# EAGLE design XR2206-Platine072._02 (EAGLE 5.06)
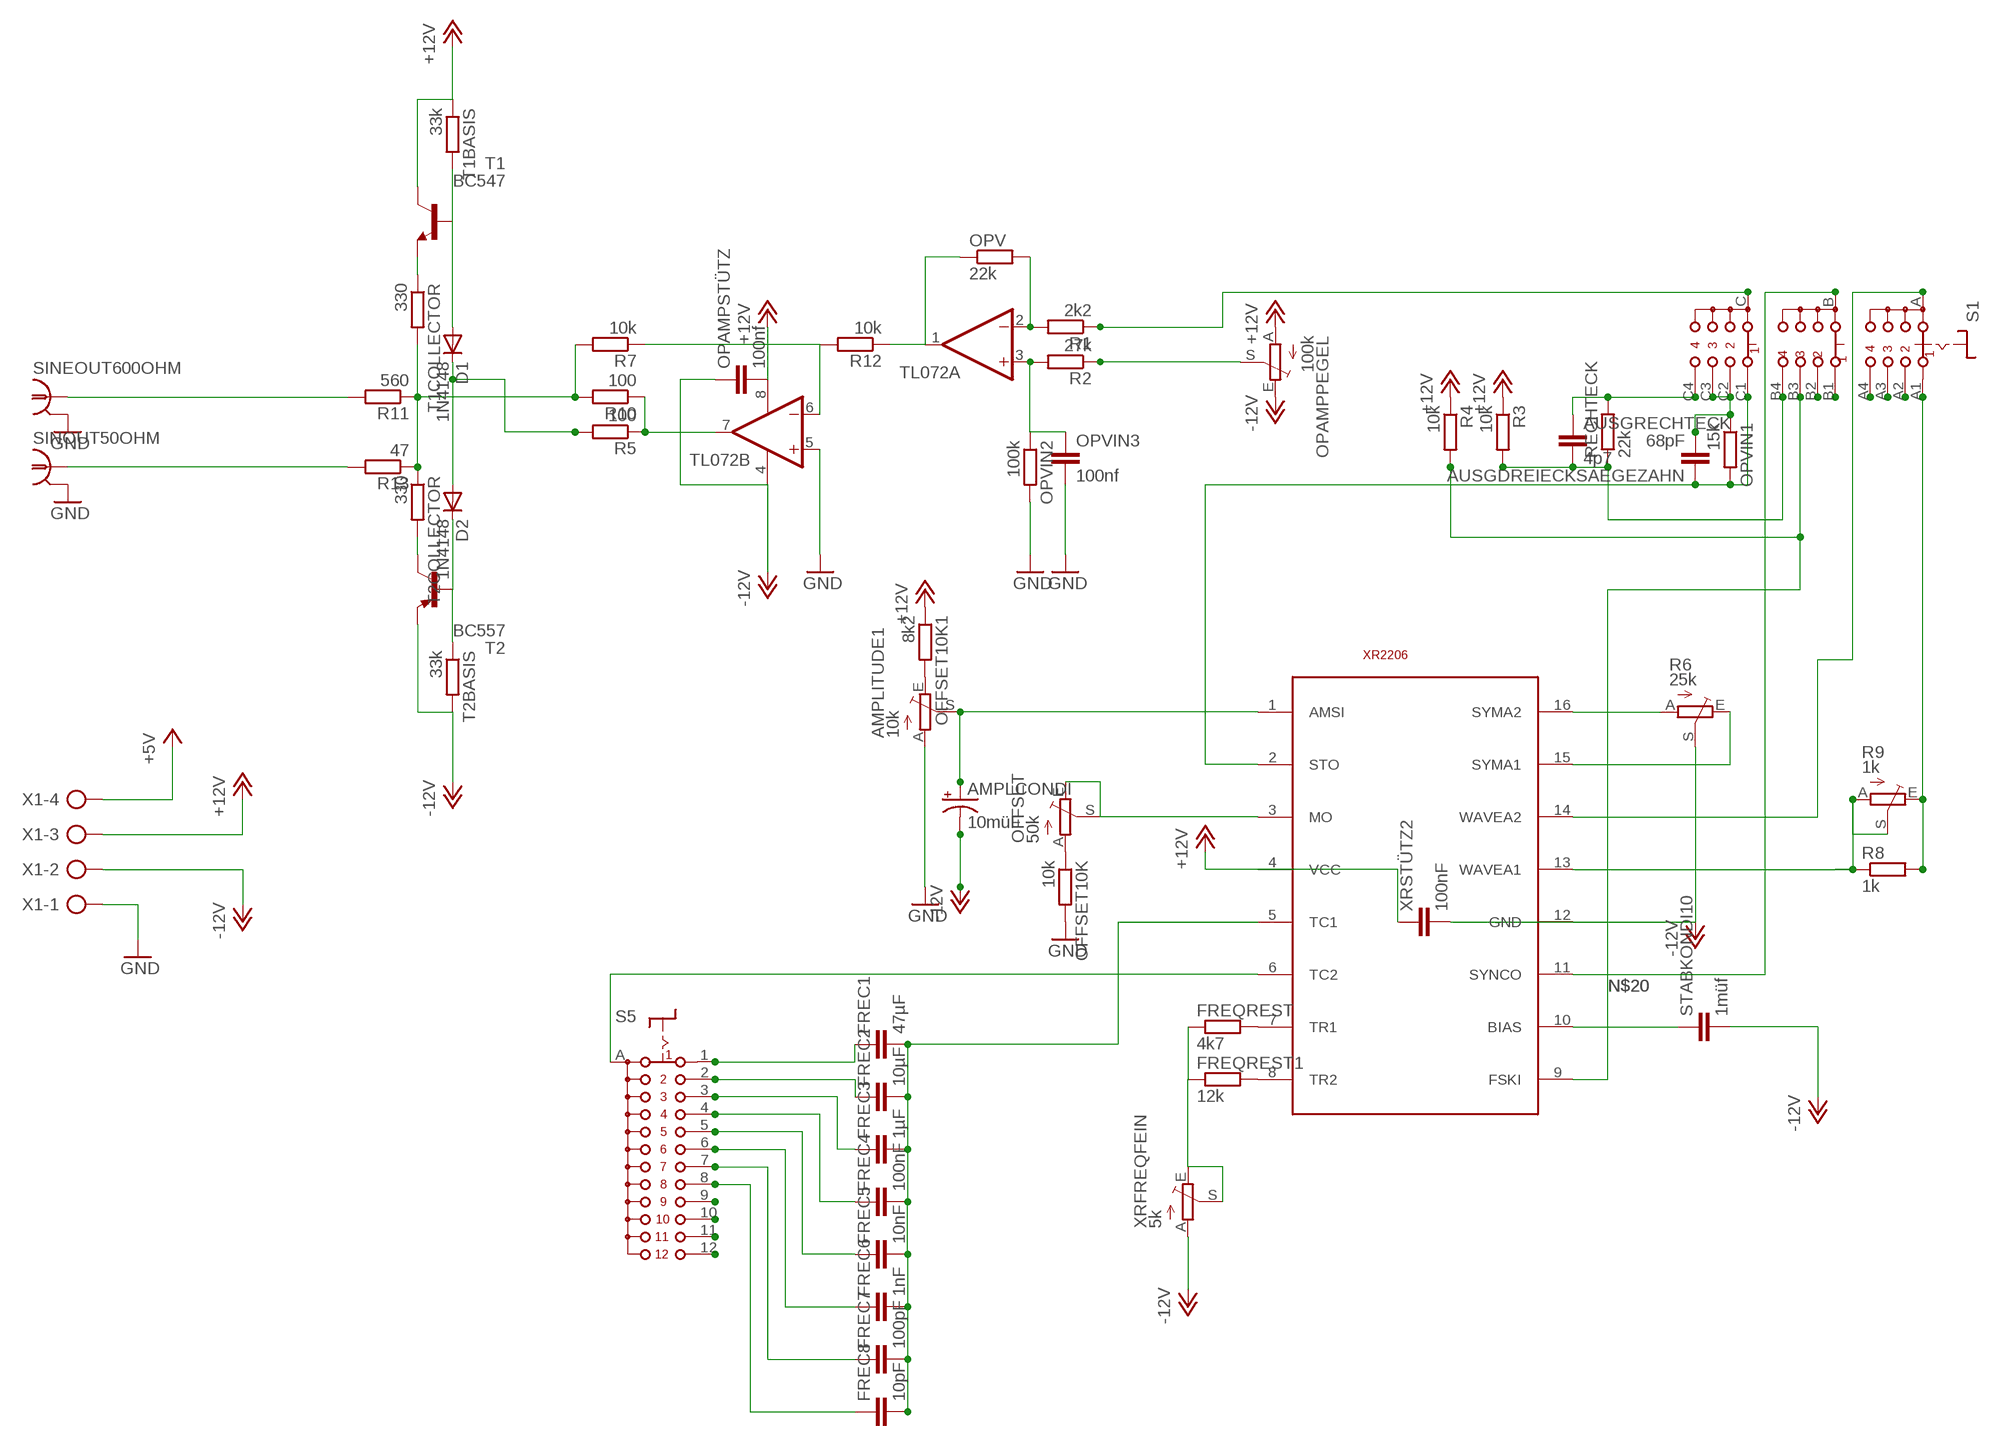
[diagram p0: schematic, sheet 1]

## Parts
AMPLCONDI  10müF  CPOL-USE2.5-5  [E2,5-5]
AMPLITUDE1  10k  TRIM_EU-CIP20C-6MM  [CIP20C-6MM]
AUSGDREIECKSAEGEZAHN  68pF  C-EUC0603  [C0603]
AUSGRECHTECK  4p7  C-EUC0603  [C0603]
D1  1N4148  DIODE-GF1  [GF1]
D2  1N4148  DIODE-GF1  [GF1]
FREC1  47µF  C-EUC1812K  [C1812K]
FREC2  10µF  C-EUC1812K  [C1812K]
FREC3  1µF  C-EUC0603  [C0603]
FREC4  100nF  C-EUC0603  [C0603]
FREC5  10nF  C-EUC0603  [C0603]
FREC6  1nF  C-EUC0603  [C0603]
FREC7  100pF  C-EUC0603  [C0603]
FREC8  10pF  C-EUC0603  [C0603]
FREQREST  4k7  R-EU_R0603  [R0603]
FREQREST1  12k  R-EU_R0603  [R0603]
OFFSET  50k  TRIM_1234-S64YW  [S64YW]
OFFSET10K  10k  R-EU_R0603  [R0603]
OFFSET10K1  8k2  R-EU_R0603  [R0603]
OPAMPPEGEL  100k  TRIM_EU-CIP20C-6MM  [CIP20C-6MM]
OPAMPSTÜTZ  100nf  C-EUC0603  [C0603]
OPV  22k  R-EU_R0603  [R0603]
OPVIN1  15k  R-EU_R0603  [R0603]
OPVIN2  100k  R-EU_R0603  [R0603]
OPVIN3  100nf  C-EUC0603  [C0603]
R1  2k2  R-EU_R0603  [R0603]
R2  27k  R-EU_R0603  [R0603]
R3  10k  R-EU_R0603  [R0603]
R4  10k  R-EU_R0603  [R0603]
R5  100  R-EU_R0603  [R0603]
R6  25k  TRIM_1234-S64YW  [S64YW]
R7  10k  R-EU_R0603  [R0603]
R8  1k  R-EU_R0603  [R0603]
R9  1k  TRIM_1234-S64YW  [S64YW]
R10  100  R-EU_R0603  [R0603]
R11  560  R-EU_R0603  [R0603]
R12  10k  R-EU_R0603  [R0603]
R13  47  R-EU_R0603  [R0603]
RECHTECK  22k  R-EU_R0603  [R0603]
S1  CK103X04  [CK103X04]
S5  CK101X12  [CK101X12]
SINEOUT600OHM  R141426  [R141426]
SINOUT50OHM  R141426  [R141426]
STABKONDI10  1müf  C-EUC0603  [C0603]
T1  BC547  BC547B-NPN-TO92-EBC  [TO92-EBC]
T1BASIS  33k  R-EU_R0603  [R0603]
T1COLLECTOR  330  R-EU_R0603  [R0603]
T2  BC557  [TO92-EBC]
T2BASIS  33k  R-EU_R0603  [R0603]
T2COLLECTOR  330  R-EU_R0603  [R0603]
TL072  LM1458N  [DIL08]
U$1  XR2206  [DIL16]
X1  AK300/4  [AK300/4]
XRFREQFEIN  5k  TRIM_EU-CIP20C-6MM  [CIP20C-6MM]
XRSTÜTZ2  100nF  C-EUC0603  [C0603]

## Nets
+5V: X1.4
+12V: OFFSET10K1.1 OPAMPPEGEL.A OPAMPSTÜTZ.2 R3.1 R4.1 T1.C T1BASIS.1 TL072.8(P:V+) U$1.4(VCC) X1.3 XRSTÜTZ2.1
-12V: AMPLCONDI.- OPAMPPEGEL.E OPAMPSTÜTZ.1 R6.S STABKONDI10.2 T2.E T2BASIS.2 TL072.4(P:V-) U$1.12(GND) X1.2 XRFREQFEIN.A XRSTÜTZ2.2
GND: AMPLITUDE1.A OFFSET10K.2 OPVIN2.2 OPVIN3.2 SINEOUT600OHM.2(GND) SINOUT50OHM.2(GND) TL072.5(B:+IN) X1.1
N$1: FREC6.1 S5.6
N$2: FREC7.1 S5.7
N$3: FREQREST.2 U$1.7(TR1)
N$4: OFFSET10K.1 OFFSET.A
N$5: FREC8.1 S5.8
N$6: R6.A U$1.16(SYMA2)
N$7: R6.E U$1.15(SYMA1)
N$8: OFFSET.E OFFSET.S U$1.3(MO)
N$9: AMPLCONDI.+ AMPLITUDE1.S U$1.1(AMSI)
N$10: R8.1 R9.A R9.S U$1.13(WAVEA1)
N$11: S5.9
N$12: R8.2 R9.E S1.A1
N$13: S5.A U$1.6(TC2)
N$14: FREC1.1 S5.1
N$15: FREC2.1 S5.2
N$16: FREC3.1 S5.3
N$17: FREC4.1 S5.4
N$18: OPV.2 R1.2 TL072.2(A:-IN)
N$19: STABKONDI10.1 U$1.10(BIAS)
N$20: OPVIN2.1 OPVIN3.1 R2.2 TL072.3(A:+IN)
N$21: S5.10
N$22: OPV.1 R12.1 TL072.1(A:OUT)
N$23: R11.2 SINEOUT600OHM.1
N$24: AMPLITUDE1.E OFFSET10K1.2
N$25: S5.11
N$26: S5.12
N$27: FREQREST1.2 U$1.8(TR2)
N$28: R7.1 R12.2 TL072.6(B:-IN)
N$29: S1.B1
N$30: FREC1.2 FREC2.2 FREC3.2 FREC4.2 FREC5.2 FREC6.2 FREC7.2 FREC8.2 U$1.5(TC1)
N$31: FREQREST1.1 FREQREST.1 XRFREQFEIN.E XRFREQFEIN.S
N$32: OPAMPPEGEL.S R2.1
N$33: S1.B U$1.11(SYNCO)
N$34: AUSGDREIECKSAEGEZAHN.1 OPVIN1.2 S1.C1 U$1.2(STO)
N$35: FREC5.1 S5.5
N$36: AUSGDREIECKSAEGEZAHN.2 OPVIN1.1 S1.C2 S1.C3
N$37: R13.2 SINOUT50OHM.1
N$38: AUSGRECHTECK.1 RECHTECK.2 S1.C4
N$39: AUSGRECHTECK.2 R3.2 RECHTECK.1 S1.B4
N$41: R4.2 S1.B3 U$1.9(FSKI)
N$42: S1.B2
N$43: S1.A4
N$44: S1.A3
N$45: S1.A2
N$46: R1.1 S1.C
N$48: S1.A U$1.14(WAVEA2)
N$49: D1.C D2.A R5.2
N$50: D1.A T1.B T1BASIS.2
N$51: D2.C T2.B T2BASIS.1
N$52: R7.2 R10.2 R11.1 R13.1 T1COLLECTOR.2 T2COLLECTOR.1
N$53: R5.1 R10.1 TL072.7(B:OUT)
N$54: T1.E T1COLLECTOR.1
N$55: T2.C T2COLLECTOR.2
Unconnected: OFFSET.S@1(S) R6.S@1(S) R9.S@1(S)

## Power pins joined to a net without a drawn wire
GND: SINEOUT600OHM.3(GND) SINEOUT600OHM.4(GND) SINEOUT600OHM.5(GND) SINOUT50OHM.3(GND) SINOUT50OHM.4(GND) SINOUT50OHM.5(GND)

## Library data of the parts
AMPLCONDI = rcl:CPOL-US: POLARIZED CAPACITOR, American symbol
AMPLITUDE1 OPAMPPEGEL XRFREQFEIN = pot:TRIM_EU-: POTENTIOMETER
AUSGDREIECKSAEGEZAHN AUSGRECHTECK FREC1-FREC8 OPAMPSTÜTZ OPVIN3 STABKONDI10 XRSTÜTZ2 = rcl:C-EU: CAPACITOR, European symbol
D1 D2 = diode:DIODE-: DIODE
FREQREST FREQREST1 OFFSET10K OFFSET10K1 OPV OPVIN1 OPVIN2 R1-R5 R7 R8 R10-R13 RECHTECK T1BASIS T1COLLECTOR T2BASIS T2COLLECTOR = rcl:R-EU_: RESISTOR, European symbol
OFFSET R6 R9 = pot:TRIM_1234-: POTENTIOMETER
S1 = switch:CK103X04: ROTARY SWITCH C&K
S5 = switch:CK101X12: ROTARY SWITCH C&K
SINEOUT600OHM SINOUT50OHM = con-coax:R141426: BNC COAX CONNECTOR Radiall 50/75 Ohm Spoerle
T1 = transistor:*-NPN-: NPN Transistror BF959 corrected 2008.03.06
T2 = transistor-pnp:BC557*: PNP Transistror
TL072 = linear:*1458: OP AMP
U$1 = linear:XR2206
X1 = con-ptr500:AK300/4: CONNECTOR

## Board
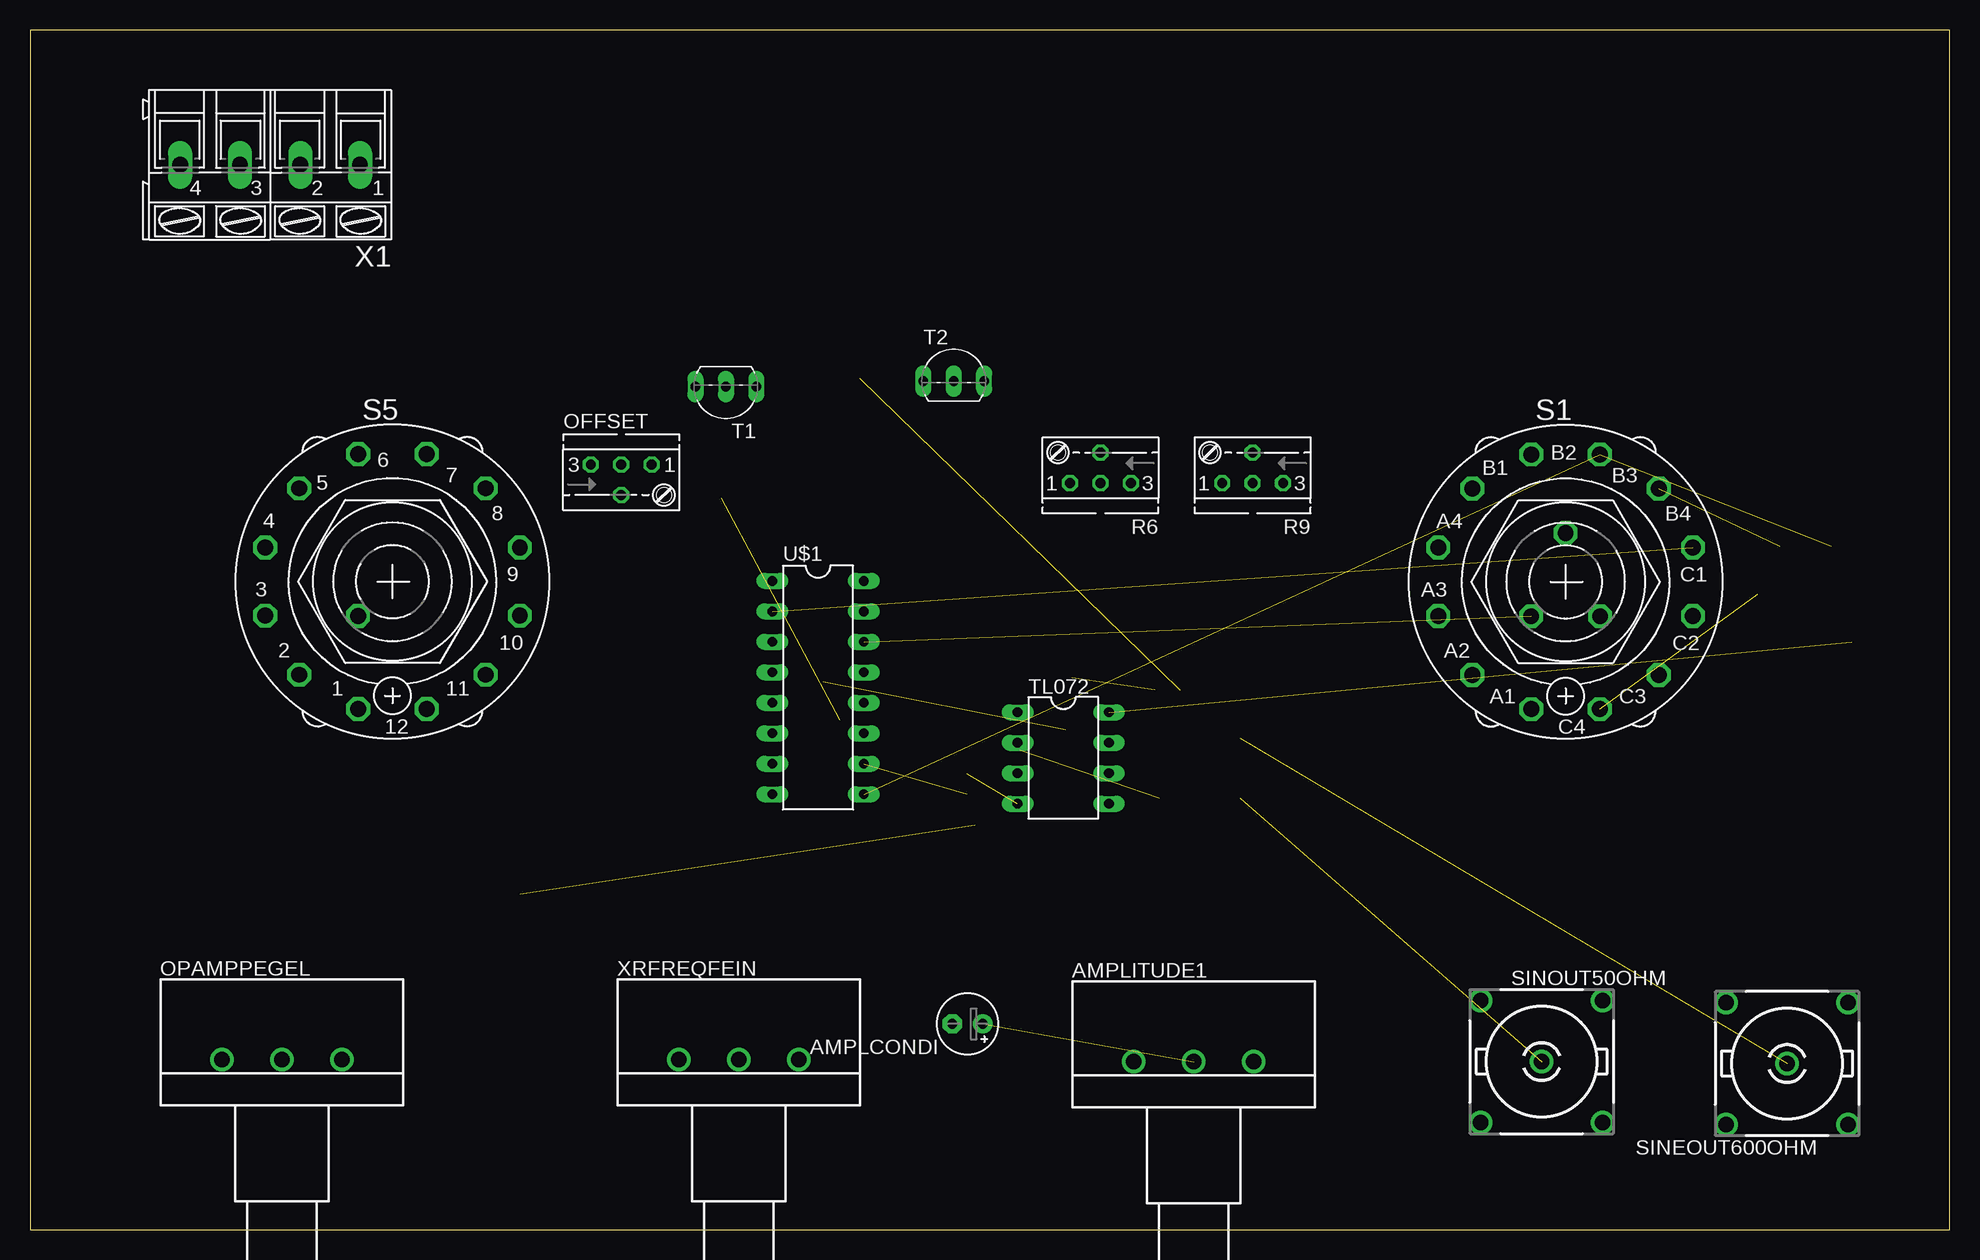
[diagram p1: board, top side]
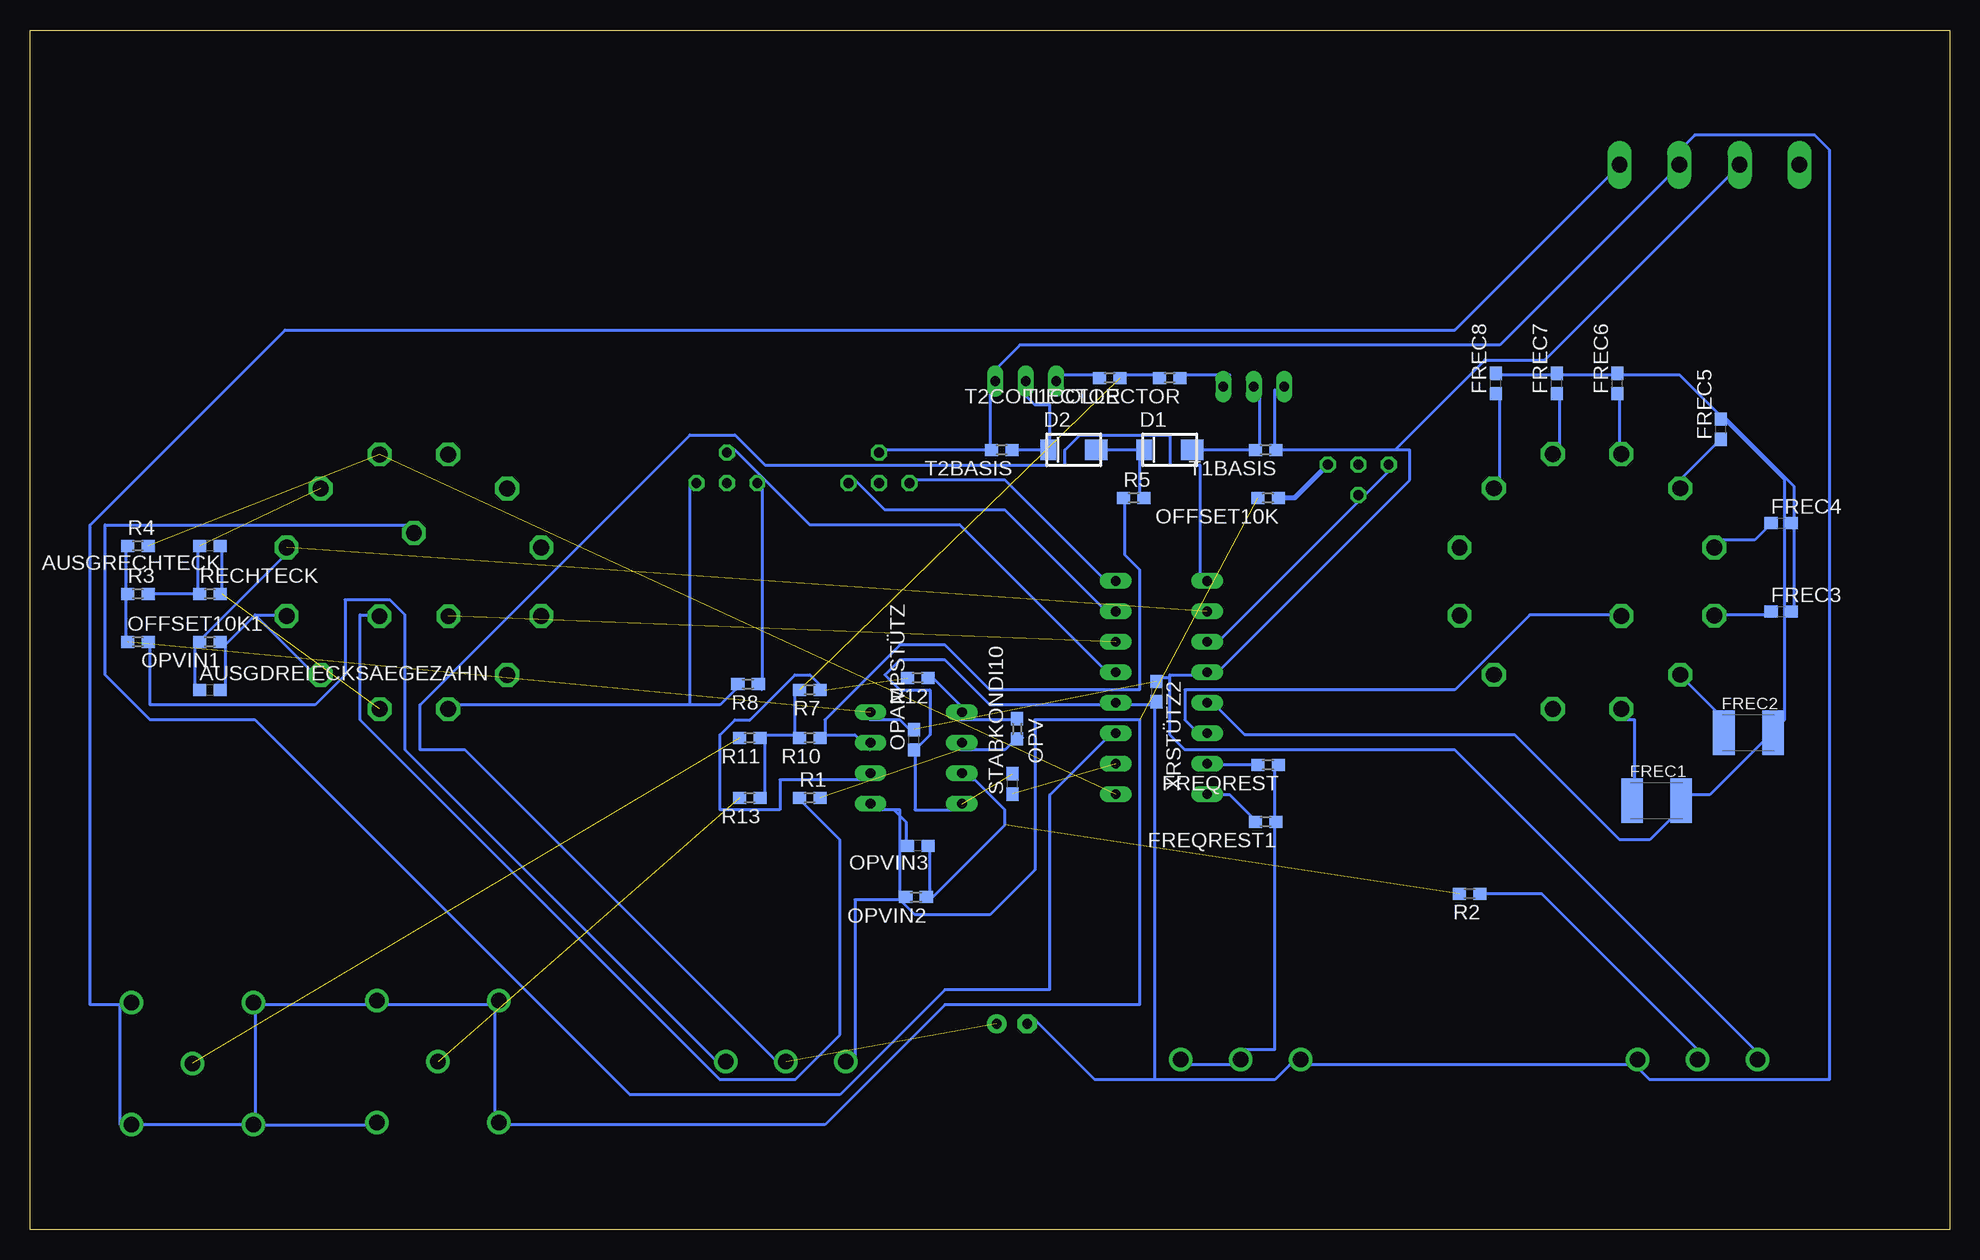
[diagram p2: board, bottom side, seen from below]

Size 160 x 100 mm. Coordinates in mm from the lower left corner, seen from the top.
Outline: 0,0 160,0 160,100 0,100 0,0
Copper layers (1*16): Top 0.035mm / dielectric 1.5mm / Bottom 0.035mm
Design rules "default": minimum track width 10mil, minimum drill 24mil, track to track 8mil, track to pad 8mil, pad to pad 8mil, via to via 8mil, smd to smd 8mil, copper to edge 40mil, drill to drill 8mil, minimum pad ring 10mil, minimum via ring 8mil, stop-mask expansion 4mil, vias tented up to drill 0mil, thermal gap 10mil

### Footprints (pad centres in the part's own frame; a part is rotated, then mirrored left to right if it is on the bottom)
E2,5-5 = drill 0.813 pad 1.6 round: + -1.27,0 | drill 0.813 pad 1.6 octagon: - 1.27,0
CIP20C-6MM = drill 1.3 pad 1.93 round: A -5,0; E 5,0; S 0,0
C0603 = smd 1.1 x 1: 1 -0.85,0; 2 0.85,0
GF1 = smd 1.85 x 1.68: A 1.87,0 | smd 1.32 x 1.68: C -2.12,0
C1812K = smd 1.8 x 3.7: 1 -2.05,0; 2 2.05,0
R0603 = smd 1.1 x 1: 1 -0.85,0; 2 0.85,0
S64YW = drill 0.813 octagon: A 2.54,1.27; E -2.54,1.27; S 0,-1.27; S@1 0,1.27
CK103X04 = drill 1.321 octagon: A -2.87,-2.87; A1 -2.845,-10.617; A2 -7.772,-7.772; A3 -10.617,-2.845; A4 -10.617,2.845; B 0,4.059; B1 -7.772,7.772; B2 -2.845,10.617; B3 2.845,10.617; B4 7.772,7.772; C 2.87,-2.87; C1 10.617,2.845; C2 10.617,-2.845; C3 7.772,-7.772; C4 2.845,-10.617
CK101X12 = drill 1.321 octagon: 1 -2.845,-10.617; 2 -7.772,-7.772; 3 -10.617,-2.845; 4 -10.617,2.845; 5 -7.772,7.772; 6 -2.845,10.617; 7 2.845,10.617; 8 7.772,7.772; 9 10.617,2.845; 10 10.617,-2.845; 11 7.772,-7.772; 12 2.845,-10.617; A -2.87,-2.87
R141426 = drill 1.295 round: 1 0,0; 2 5.08,5.08; 3 -5.08,5.08; 4 -5.08,-5.08; 5 5.08,-5.08
TO92-EBC = drill 0.813 long: B 0,-1.27; C 2.54,-1.27; E -2.54,-1.27
TO92-EBC' = drill 0.813 long: B 0,-1.27; C -2.54,-1.27; E 2.54,-1.27
DIL08 = drill 0.813 long: 1 -3.81,-3.81; 2 -1.27,-3.81; 3 1.27,-3.81; 4 3.81,-3.81; 5 3.81,3.81; 6 1.27,3.81; 7 -1.27,3.81; 8 -3.81,3.81
DIL16 = drill 0.813 long: 1 -8.89,-3.81; 2 -6.35,-3.81; 3 -3.81,-3.81; 4 -1.27,-3.81; 5 1.27,-3.81; 6 3.81,-3.81; 7 6.35,-3.81; 8 8.89,-3.81; 9 8.89,3.81; 10 6.35,3.81; 11 3.81,3.81; 12 1.27,3.81; 13 -1.27,3.81; 14 -3.81,3.81; 15 -6.35,3.81; 16 -8.89,3.81
AK300/4 = drill 1.321 long: 1 -7.493,0; 2 -2.515,0; 3 2.515,0; 4 7.493,0

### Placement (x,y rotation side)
AMPLCONDI  78.15,17.14 180 top
AMPLITUDE1  97,14 0 top
AUSGDREIECKSAEGEZAHN  145,45 0 bottom
AUSGRECHTECK  145,57 180 bottom
D1  65,65 0 bottom
D2  73,65 0 bottom
FREC1  24.41,35.76 0 bottom
FREC2  16.76,41.41 0 bottom
FREC3  14.03,51.52 0 bottom
FREC4  14.03,58.9 0 bottom
FREC5  19.05,66.72 90 bottom
FREC6  27.67,70.53 90 bottom
FREC7  32.75,70.53 90 bottom
FREC8  37.83,70.53 90 bottom
FREQREST  56.8,38.75 180 bottom
FREQREST1  57,34 180 bottom
OFFSET  49.28,62.5 0 top
OFFSET10K  56.8,60.99 180 bottom
OFFSET10K1  151,49 0 bottom
OPAMPPEGEL  20.99,14.16 0 top
OPAMPSTÜTZ  86.31,40.82 90 bottom
OPV  77.71,41.74 270 bottom
OPVIN1  145,49 180 bottom
OPVIN2  86.15,27.71 180 bottom
OPVIN3  86,32 180 bottom
R1  95,36 0 bottom
R2  40,28 180 bottom
R3  151,53 0 bottom
R4  151,57 0 bottom
R5  68,61 0 bottom
R6  89.23,63.5 180 top
R7  95,45 180 bottom
R8  100.15,45.47 180 bottom
R9  101.91,63.5 180 top
R10  95,41 180 bottom
R11  100,41 180 bottom
R12  86,46 180 bottom
R13  100,36 180 bottom
RECHTECK  145,53 0 bottom
S1  128,54 0 top
S5  30.21,54.02 0 top
SINEOUT600OHM  146.46,13.84 180 top
SINOUT50OHM  126,14 0 top
STABKONDI10  78.1,37.15 90 bottom
T1  58,69 180 top
T1BASIS  57,65 180 bottom
T1COLLECTOR  65,71 180 bottom
T2  BC557  [TO92-EBC']  77,72 0 top
T2BASIS  79,65 180 bottom
T2COLLECTOR  70,71 180 bottom
TL072  86.13,39.31 270 top
U$1  65.69,45.18 270 top
X1  20.01,88.76 180 top
XRFREQFEIN  59.09,14.16 0 top
XRSTÜTZ2  66.09,44.85 270 bottom

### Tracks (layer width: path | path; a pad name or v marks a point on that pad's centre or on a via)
+12V  (2 unrouted)
  Bottom 0.254: T1.C 55,70 56.25,70 56.25,65 T1BASIS.1 46.25,65 | 46.25,65 45,65 45,62.5 61.25,46.25 U$1.4 62.5,46.25 65,46.25 65,46 | 65,46 65,41.25 63.75,40 41.25,40 16.25,15 OPAMPPEGEL.A | 46.25,65 38.75,72.5 33.75,72.5 X1.3 | OPAMPSTÜTZ.2 86.25,41.25 87.5,42.5 90,42.5 TL072.8 | 152,53 152,49 OFFSET10K1.1 | 152,53 152,57 R4.1 | 152,53 R3.1 | 65,46 66,46 XRSTÜTZ2.1
-12V  (1 unrouted)
  Bottom 0.254: 80,65 80,70 T2.E 80,71.25 77.5,73.75 37.5,73.75 22.5,88.75 X1.2 22.5,90 21.25,91.25 11.25,91.25 10,90 10,12.5 25,12.5 26.25,13.75 | 80,65 88.75,65 R6.S | 80,65 T2BASIS.2 | 86.25,40 86.25,35 82.5,35 TL072.4 | 66.25,43.75 68.75,43.75 U$1.12 70,43.75 80,43.75 83.75,47.5 87.5,47.5 88.75,46.25 87.5,45 85,45 85,41.25 86.25,40 | 66.25,12.5 56.25,12.5 55,13.75 XRFREQFEIN.A 53.75,13.75 26.25,13.75 | 66.25,12.5 71.25,12.5 76.25,17.5 AMPLCONDI.- | 66.25,12.5 66.25,43.75 | 66.25,43.75 XRSTÜTZ2.2 | 86.25,40 OPAMPSTÜTZ.1 | 26.25,13.75 OPAMPPEGEL.E
GND  (1 unrouted)
  Bottom 0.254: 87.5,27.5 87.5,35 88,35 | 88,35 90,35 TL072.5 | 87.5,27.5 91.25,27.5 91.25,13.75 AMPLITUDE1.A | 141.25,8.75 131.25,8.75 SINOUT50OHM.5 | 121.25,18.75 121.25,8.75 SINOUT50OHM.4 120,8.75 93.75,8.75 83.75,18.75 67.5,18.75 67.5,42.5 76.25,42.5 76.25,30 80,26.25 86.25,26.25 87.5,27.5 | 121.25,18.75 131.25,18.75 | 121.25,18.75 SINOUT50OHM.3 | 131.25,18.75 141.25,18.75 | 131.25,18.75 SINOUT50OHM.2 | 141.25,18.75 141.25,8.75 | 141.25,18.75 SINEOUT600OHM.5 | 87.5,27.5 OPVIN2.2 | 152.5,18.75 152.5,8.75 SINEOUT600OHM.3 151.25,8.75 141.25,8.75 | 152.5,18.75 155,18.75 155,58.75 138.75,75 41.25,75 X1.1 | 152.5,18.75 SINEOUT600OHM.4 | 141.25,8.75 SINEOUT600OHM.2 | 88,35 87,34 87,32 OPVIN3.2
N$1
  Bottom 0.254: FREC6.1 27.5,70 27.5,65 S5.6
N$2
  Bottom 0.254: FREC7.1 32.5,70 32.5,65 S5.7
N$3
  Bottom 0.254: 57.5,38.75 FREQREST.2 61.25,38.75 U$1.7
N$4
  Bottom 0.406: OFFSET10K.1 54.6,60.99 OFFSET.A
N$5
  Bottom 0.254: FREC8.1 37.5,70 37.5,62.5 S5.8
N$6
  Bottom 0.254: U$1.16 70,53.75 78.75,62.5 86.25,62.5 R6.A
N$7
  Bottom 0.254: U$1.15 70,51.25 78.75,60 88.75,60 91.25,62.5 R6.E
N$8
  Bottom 0.254: 48.75,61.25 46.25,63.75 OFFSET.E | 48.75,61.25 61.25,48.75 U$1.3 | 48.75,61.25 OFFSET.S
N$9  (1 unrouted)
  Bottom 0.254: U$1.1 62.5,53.75 62.5,63.75 65,63.75 65,66.25 72.5,66.25 73.75,65 73.75,63.75 98.75,63.75 101.25,66.25 105,66.25 127.5,43.75 127.5,40 123.75,40 97.5,13.75 AMPLITUDE1.S
N$10
  Bottom 0.254: 98.75,62.5 95,58.75 82.5,58.75 70,46.25 U$1.13 | 98.75,62.5 101.25,65 R9.S | 98.75,62.5 R9.A 99,62 99,45 R8.1
N$12
  Bottom 0.254: 105,43.75 125,43.75 S1.A1 | 105,43.75 102.5,43.75 101.25,45 R8.2 | 105,43.75 105,62.5 R9.E
N$13
  Bottom 0.254: U$1.6 62.5,41.25 63.75,42.5 63.75,45 41.25,45 35,51.25 27.5,51.25 S5.A
N$14
  Bottom 0.254: FREC1.1 26.25,36.25 26.25,42.5 27.5,42.5 S5.1
N$15
  Bottom 0.254: FREC2.1 18.75,42.5 22.5,46.25 S5.2
N$16
  Bottom 0.254: FREC3.1 15,51.25 18.75,51.25 S5.3
N$17
  Bottom 0.254: FREC4.1 15,58.75 16.25,57.5 20,57.5 S5.4
N$18  (1 unrouted)
  Bottom 0.254: 77.25,41 OPV.2 77.5,41.25 78.75,40 82.5,40 TL072.2
N$19  (1 unrouted)
N$20  (1 unrouted)
  Bottom 0.254: TL072.3 82.5,37.5 81.25,37.5 78.75,35 78.75,33.75 85,27.5 OPVIN2.1 85,28 85,32 OPVIN3.1
N$22
  Bottom 0.254: OPV.1 77.5,42.5 82.5,42.5 TL072.1 82.5,43.75 85,46.25 R12.1
N$23  (1 unrouted)
N$24
  Bottom 0.254: OFFSET10K1.2 150,48.75 150,43.75 136.25,43.75 133.75,46.25 133.75,52.5 130,52.5 128.75,51.25 128.75,40 102.5,13.75 AMPLITUDE1.E
N$27
  Bottom 0.254: FREQREST1.2 57.5,33.75 60,36.25 61.25,36.25 U$1.8
N$28  (1 unrouted)
  Bottom 0.254: R7.1 93.75,45 95,46.25 96.25,46.25 100,42.5 101.25,42.5 102.5,41.25 102.5,35 97.5,35 97.5,37.5 90,37.5 TL072.6
N$30
  Bottom 0.254: 18.75,67.5 22.5,71.25 27.5,71.25 | 27.5,71.25 32.5,71.25 | 27.5,71.25 FREC6.2 | 32.5,71.25 37.5,71.25 FREC8.2 | 32.5,71.25 FREC7.2 | U$1.5 61.25,43.75 58.75,41.25 36.25,41.25 27.5,32.5 25,32.5 22.5,35 FREC1.2 22.5,36.25 20,36.25 15,41.25 FREC2.2 15,42.5 13.75,42.5 13.75,62.5 18.75,67.5 | 18.75,67.5 FREC5.2 19,68 13,62 13,59 | 13,59 13,52 FREC3.2 | 13,59 FREC4.2
N$31
  Bottom 0.254: 56.25,33.75 56.25,38.75 FREQREST.1 | 56.25,33.75 56.25,15 58.75,15 XRFREQFEIN.S 60,13.75 63.75,13.75 XRFREQFEIN.E | 56.25,33.75 FREQREST1.1
N$32
  Bottom 0.254: R2.1 34,28 21,15 OPAMPPEGEL.S
N$33
  Bottom 0.254: U$1.11 70,41.25 75,36.25 75,20 83.75,20 92.5,11.25 110,11.25 141.25,42.5 150,42.5 153.75,46.25 153.75,58.75 127.5,58.75 S1.B
N$34  (1 unrouted)
  Bottom 0.254: 146.25,48.75 146.25,45 AUSGDREIECKSAEGEZAHN.1 | 146.25,48.75 138.75,56.25 S1.C1 | 146.25,48.75 OPVIN1.2
N$35
  Bottom 0.254: FREC5.1 18.75,66.25 22.5,62.5 S5.5
N$36
  Bottom 0.254: 143.75,48.75 143.75,45 AUSGDREIECKSAEGEZAHN.2 | 141.25,51.25 143.75,48.75 | 141.25,51.25 138.75,51.25 S1.C2 | 143.75,48.75 OPVIN1.1 | 141.25,51.25 136.25,46.25 S1.C3
N$37  (1 unrouted)
N$38  (1 unrouted)
  Bottom 0.254: RECHTECK.2 144,53 144,57 AUSGRECHTECK.1
N$39  (1 unrouted)
  Bottom 0.254: 146,53 146,57 AUSGRECHTECK.2 | 146,53 R3.2 | RECHTECK.1 146,53
N$41  (2 unrouted)
N$46
  Bottom 0.254: R1.1 96.25,36.25 92.5,32.5 92.5,16.25 96.25,12.5 102.5,12.5 132.5,42.5 132.5,51.25 131.25,51.25 S1.C
N$48  (1 unrouted)
N$49
  Bottom 0.254: 67.5,65 67.5,61.25 R5.2 | 67.5,65 D2.A 71.25,65 | 67.5,65 D1.C
N$50
  Bottom 0.254: T1.B 57.5,70 57.5,65 T1BASIS.2 D1.A
N$51
  Bottom 0.254: T2.B 77.5,70 76.25,68.75 75,68.75 75,65 D2.C T2BASIS.1
N$52  (1 unrouted)
  Bottom 0.254: T1COLLECTOR.2 66.25,71.25 68.75,71.25 T2COLLECTOR.1 | 98.75,41.25 98.75,36.25 R13.1 | 98.75,41.25 96.25,41.25 | 98.75,41.25 R11.1 | 96.25,41.25 96.25,45 R7.2 | 96.25,41.25 R10.2
N$53
  Bottom 0.254: 93.75,41.25 93.75,42.5 87.5,48.75 83.75,48.75 80,45 67.5,45 67.5,55 68.75,56.25 68.75,61.25 R5.1 | 93.75,41.25 91.25,41.25 90,40 TL072.7 | 93.75,41.25 R10.1
N$54
  Bottom 0.254: T1COLLECTOR.1 63.75,71.25 60,71.25 T1.E
N$55
  Bottom 0.254: T2COLLECTOR.2 71.25,71.25 75,71.25 T2.C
